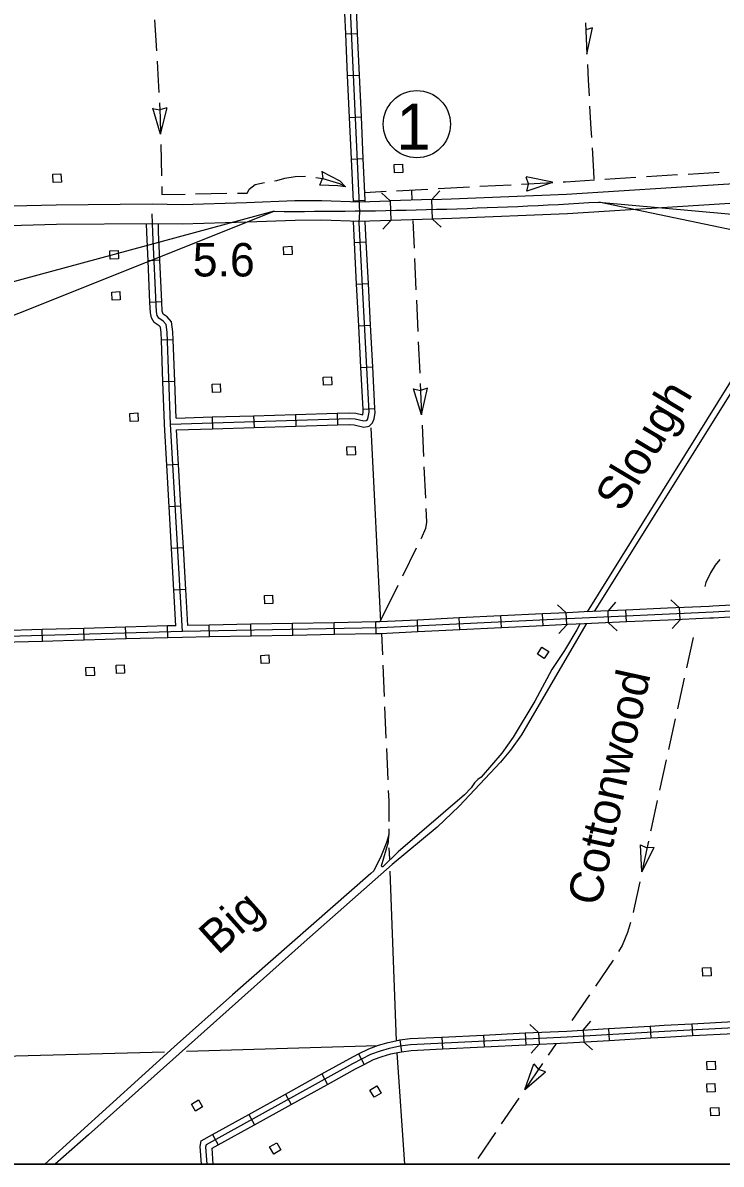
# Model space of a CAD drawing. Extents: x -0.3 to 2.65, y 0 to 1.9.
# Drawn here: x 0.6457 to 0.7514, y 0.1443 to 0.3171 of the extents above; entities that cross this region are included whole.
import ezdxf

# ---------------------------------------------------------------- set-up
doc = ezdxf.new("R2010")
doc.units = 0
for name, color, linetype in [('Default', 7, 'Continuous'), ('DSN_DRFT_DNC', 7, 'Continuous'), ('Level 12', 7, 'Continuous'), ('Level 14', 7, 'Continuous'), ('Level 15', 7, 'Continuous'), ('Level 16', 7, 'Continuous'), ('Level 19', 7, 'Continuous'), ('Level 20', 7, 'Continuous'), ('Level 21', 7, 'Continuous'), ('Level 29', 7, 'Continuous'), ('Level 30', 7, 'Continuous'), ('Level 6', 7, 'Continuous'), ('SHET_Annotations', 7, 'Continuous')]:
    doc.layers.add(name, color=color, linetype=linetype)

msp = doc.modelspace()

# ---------------------------------------------------------------- linework, layer by layer
at = {"layer": 'Default'}
for points in [[(0.97177, 0.24009), (0.73293, 0.28998), (0.80083, 0.28386)], [(0.45189, 0.196), (0.68371, 0.28858), (0.61638, 0.27038)]]:
    msp.add_lwpolyline(points, dxfattribs=at)
msp.add_arc((0.68669, 1.04739), 0.75882, 269.77499, 273.49367, dxfattribs=at)
at = {"layer": 'DSN_DRFT_DNC'}
msp.add_lwpolyline([(0.38477, 0.54167), (1.0319, 0.54167), (1.0319, 0.1443), (0.38477, 0.1443)], close=True, dxfattribs=at)
at = {"layer": 'Level 12'}
for p, q in [((0.73197, 0.31638), (0.73093, 0.31604)), ((0.73111, 0.31236), (0.73197, 0.31638)), ((0.66746, 0.30427), (0.66642, 0.30393)), ((0.66653, 0.30025), (0.66751, 0.30424)), ((0.66533, 0.30415), (0.6664, 0.30393)), ((0.66653, 0.30025), (0.66538, 0.30419)), ((0.69094, 0.29464), (0.69109, 0.29356)), ((0.69067, 0.29254), (0.69108, 0.29355)), ((0.72186, 0.29382), (0.72221, 0.29279)), ((0.72591, 0.29299), (0.72189, 0.2938)), ((0.72591, 0.29296), (0.72202, 0.29165)), ((0.72202, 0.29162), (0.72224, 0.29269)), ((0.70482, 0.26168), (0.70589, 0.26144)), ((0.70607, 0.25776), (0.70482, 0.26168)), ((0.70695, 0.26177), (0.70591, 0.26144)), ((0.70607, 0.25776), (0.70695, 0.26177)), ((0.73922, 0.19266), (0.7402, 0.19216)), ((0.73944, 0.18855), (0.73922, 0.19266)), ((0.73944, 0.18855), (0.7413, 0.19221)), ((0.7413, 0.19221), (0.74021, 0.19216)), ((0.7217, 0.15559), (0.72306, 0.15946)), ((0.72306, 0.15946), (0.72377, 0.15863)), ((0.7217, 0.15559), (0.72482, 0.15826)), ((0.72482, 0.15826), (0.72379, 0.15862))]:
    msp.add_line(p, q, dxfattribs=at)
for points in [[(0.66559, 0.31759), (0.66589, 0.31286)], [(0.73087, 0.3171), (0.73111, 0.31236)], [(0.66599, 0.31129), (0.66612, 0.30929), (0.66627, 0.30656)], [(0.73119, 0.31079), (0.73132, 0.30842)], [(0.73132, 0.30842), (0.73144, 0.30605)], [(0.66635, 0.30498), (0.66648, 0.30272), (0.66653, 0.30025)], [(0.73152, 0.30448), (0.7317, 0.30109), (0.73178, 0.29974)], [(0.66657, 0.29867), (0.66667, 0.29393)], [(0.73188, 0.29817), (0.7321, 0.2946), (0.73213, 0.29344)], [(0.68381, 0.29321), (0.68415, 0.29326), (0.68535, 0.29358), (0.68692, 0.29386), (0.68847, 0.29389), (0.68847, 0.29389)], [(0.69094, 0.29462), (0.69367, 0.29319), (0.69455, 0.29228), (0.69339, 0.29243), (0.69065, 0.29252)], [(0.74011, 0.29383), (0.74484, 0.29413)], [(0.74642, 0.29422), (0.75115, 0.29452)], [(0.66671, 0.29235), (0.66674, 0.29114), (0.67026, 0.29119)], [(0.67816, 0.29132), (0.67967, 0.29134), (0.67971, 0.2914), (0.67994, 0.29195), (0.68088, 0.29263), (0.68225, 0.29294)], [(0.69004, 0.29369), (0.69109, 0.29355), (0.69362, 0.29277), (0.69454, 0.29231)], [(0.70857, 0.29203), (0.7133, 0.29228)], [(0.71488, 0.29236), (0.71961, 0.29261)], [(0.72119, 0.2927), (0.72592, 0.29295)], [(0.7275, 0.29303), (0.72784, 0.29305), (0.73223, 0.29333)], [(0.73381, 0.29343), (0.73853, 0.29373)], [(0.67184, 0.29122), (0.67658, 0.2913)], [(0.69747, 0.29144), (0.70069, 0.29161)], [(0.70226, 0.29169), (0.70699, 0.29194)], [(0.70453, 0.29169), (0.70459, 0.29038)], [(0.70473, 0.2872), (0.70492, 0.28301)], [(0.70499, 0.28143), (0.70521, 0.2767)], [(0.70528, 0.27512), (0.70549, 0.27038)], [(0.70557, 0.26881), (0.70578, 0.26407)], [(0.70585, 0.26249), (0.70607, 0.25776)], [(0.70614, 0.25618), (0.70635, 0.25145)], [(0.70642, 0.24987), (0.70664, 0.24514)], [(0.70671, 0.24356), (0.7068, 0.2415), (0.70665, 0.24056), (0.70599, 0.23905), (0.70595, 0.23898)], [(0.70526, 0.23757), (0.70316, 0.23332)], [(0.75125, 0.23583), (0.75052, 0.23499), (0.7498, 0.23381), (0.74913, 0.23238), (0.74895, 0.23174)], [(0.70246, 0.2319), (0.69976, 0.22641)], [(0.69998, 0.22462), (0.70012, 0.2214)], [(0.7472, 0.22404), (0.74618, 0.21942)], [(0.70019, 0.21982), (0.70039, 0.21509)], [(0.74584, 0.21787), (0.74482, 0.21325)], [(0.70046, 0.21351), (0.70067, 0.20877)], [(0.74448, 0.2117), (0.74347, 0.20708)], [(0.70074, 0.2072), (0.70095, 0.20246)], [(0.74313, 0.20553), (0.74211, 0.2009)], [(0.70102, 0.20088), (0.70109, 0.19928), (0.7011, 0.19615)], [(0.74177, 0.19936), (0.74078, 0.19487), (0.74075, 0.19473)], [(0.74042, 0.19319), (0.73944, 0.18855)], [(0.73911, 0.18701), (0.73823, 0.18289), (0.7381, 0.18238)], [(0.73772, 0.18085), (0.73726, 0.17935), (0.73645, 0.1774), (0.7359, 0.17649)], [(0.73506, 0.17516), (0.73239, 0.17124)], [(0.7315, 0.16994), (0.72882, 0.16602)], [(0.72647, 0.16257), (0.72526, 0.1608)], [(0.72437, 0.1595), (0.7217, 0.15558)], [(0.72081, 0.15428), (0.71814, 0.15037)], [(0.71725, 0.14906), (0.71458, 0.14515)]]:
    msp.add_lwpolyline(points, dxfattribs=at)
at = {"layer": 'Level 14'}
for points in [[(0.76951, 0.2906), (0.75254, 0.2623), (0.73116, 0.2279)], [(0.7709, 0.29104), (0.75336, 0.26181), (0.7322, 0.22797)], [(0.73006, 0.22614), (0.72958, 0.22522), (0.72769, 0.22205), (0.72579, 0.21917), (0.72322, 0.21441), (0.71995, 0.20894), (0.7182, 0.20651), (0.71507, 0.20287), (0.7146, 0.20254), (0.71408, 0.202), (0.71356, 0.20126), (0.71257, 0.20022), (0.70253, 0.19155), (0.70018, 0.1893), (0.70003, 0.18928), (0.7, 0.18943), (0.70106, 0.19308), (0.7011, 0.19415), (0.70074, 0.19298), (0.69996, 0.19098), (0.69882, 0.18871), (0.69838, 0.18827), (0.6774, 0.1699), (0.66857, 0.16202), (0.64901, 0.14427)], [(0.73096, 0.22598), (0.72119, 0.20931), (0.71952, 0.20699), (0.718, 0.20515), (0.71174, 0.19849), (0.7084, 0.1953), (0.70163, 0.18967), (0.6883, 0.1779), (0.65563, 0.14874), (0.65057, 0.14427)], [(0.73106, 0.22614), (0.73096, 0.22598)], [(0.7011, 0.19504), (0.7011, 0.19415)], [(0.7011, 0.19504), (0.7011, 0.19415)], [(0.7011, 0.19457), (0.7011, 0.19415)]]:
    msp.add_lwpolyline(points, dxfattribs=at)
at = {"layer": 'Level 15'}
for p, q in [((0.69457, 0.31543), (0.69637, 0.31551)), ((0.69486, 0.30912), (0.69666, 0.3092)), ((0.69515, 0.3028), (0.69695, 0.30289)), ((0.69544, 0.29649), (0.69724, 0.29658)), ((0.69573, 0.29018), (0.69753, 0.29026)), ((0.69589, 0.28387), (0.69768, 0.28396)), ((0.66643, 0.28116), (0.66464, 0.28108)), ((0.69622, 0.27756), (0.69801, 0.27765)), ((0.66671, 0.27485), (0.66492, 0.27477)), ((0.69655, 0.27125), (0.69834, 0.27134)), ((0.66845, 0.26913), (0.66665, 0.26907)), ((0.69688, 0.26494), (0.69867, 0.26503)), ((0.66867, 0.26282), (0.66688, 0.26275)), ((0.68063, 0.25762), (0.68069, 0.25583)), ((0.68695, 0.25782), (0.687, 0.25603)), ((0.69326, 0.25802), (0.69332, 0.25622)), ((0.6972, 0.25863), (0.699, 0.25872)), ((0.67432, 0.25743), (0.67437, 0.25563)), ((0.66926, 0.25021), (0.66747, 0.25011)), ((0.66962, 0.24391), (0.66783, 0.2438)), ((0.66999, 0.2376), (0.66819, 0.2375)), ((0.67035, 0.23129), (0.66855, 0.23119)), ((0.73708, 0.22639), (0.737, 0.22818)), ((0.74523, 0.22675), (0.74515, 0.22854)), ((0.70552, 0.22489), (0.70544, 0.22668)), ((0.71184, 0.2252), (0.71175, 0.22699)), ((0.71815, 0.2255), (0.71806, 0.2273)), ((0.72446, 0.22581), (0.72437, 0.2276)), ((0.72804, 0.22599), (0.72796, 0.22778)), ((0.73438, 0.22627), (0.7343, 0.22806)), ((0.64866, 0.22344), (0.64861, 0.22524)), ((0.65498, 0.22363), (0.65493, 0.22542)), ((0.6613, 0.22381), (0.66124, 0.2256)), ((0.66761, 0.22399), (0.66756, 0.22578)), ((0.67392, 0.22413), (0.67389, 0.22592)), ((0.68024, 0.22425), (0.6802, 0.22604)), ((0.68655, 0.22436), (0.68652, 0.22616)), ((0.69287, 0.22448), (0.69284, 0.22628)), ((0.69919, 0.2246), (0.69915, 0.22639)), ((0.72377, 0.16423), (0.72385, 0.16247)), ((0.73053, 0.16456), (0.73062, 0.1628)), ((0.73437, 0.16482), (0.73447, 0.16302)), ((0.74068, 0.16519), (0.74078, 0.1634)), ((0.74699, 0.16554), (0.74708, 0.16375)), ((0.70276, 0.16308), (0.70301, 0.1613)), ((0.70914, 0.16353), (0.70923, 0.16173)), ((0.71545, 0.16383), (0.71554, 0.16204)), ((0.72176, 0.16414), (0.72185, 0.16234)), ((0.69653, 0.16097), (0.69735, 0.15937)), ((0.69096, 0.15793), (0.69183, 0.15636)), ((0.68543, 0.15487), (0.6863, 0.1533)), ((0.6799, 0.15181), (0.68077, 0.15024)), ((0.67438, 0.14875), (0.67525, 0.14718))]:
    msp.add_line(p, q, dxfattribs=at)
for points in [[(0.69662, 0.28688), (0.69669, 0.28847), (0.69377, 0.35203)], [(0.69457, 0.31543), (0.69428, 0.32174)], [(0.69637, 0.31551), (0.69608, 0.32182)], [(0.69486, 0.30912), (0.69457, 0.31543)], [(0.69666, 0.3092), (0.69637, 0.31551)], [(0.69515, 0.3028), (0.69486, 0.30912)], [(0.69695, 0.30289), (0.69666, 0.3092)], [(0.69544, 0.29649), (0.69515, 0.3028)], [(0.69724, 0.29658), (0.69695, 0.30289)], [(0.69574, 0.29005), (0.69544, 0.29649)], [(0.69753, 0.29026), (0.69724, 0.29658)], [(0.69754, 0.29004), (0.69753, 0.29026)], [(0.66536, 0.28539), (0.66527, 0.2882)], [(0.69589, 0.28387), (0.69573, 0.28705)], [(0.69768, 0.28396), (0.69752, 0.28705)], [(0.66464, 0.28108), (0.66445, 0.28535), (0.6644, 0.28669)], [(0.66983, 0.22493), (0.66803, 0.25635), (0.66752, 0.27025), (0.66736, 0.27144), (0.66692, 0.27193), (0.66627, 0.27238), (0.66603, 0.2728), (0.6659, 0.27334), (0.66536, 0.28539)], [(0.66643, 0.28116), (0.66624, 0.28542), (0.6662, 0.28668)], [(0.66803, 0.25635), (0.69521, 0.2572), (0.69599, 0.25716), (0.69733, 0.25683), (0.69767, 0.25689), (0.69785, 0.25707), (0.69798, 0.25739), (0.69811, 0.25817), (0.69662, 0.28688)], [(0.69622, 0.27756), (0.69589, 0.28387)], [(0.69801, 0.27765), (0.69768, 0.28396)], [(0.66492, 0.27477), (0.66464, 0.28108)], [(0.66671, 0.27485), (0.66643, 0.28116)], [(0.69655, 0.27125), (0.69622, 0.27756)], [(0.69834, 0.27134), (0.69801, 0.27765)], [(0.66845, 0.26913), (0.6684, 0.27032), (0.6682, 0.27183), (0.66751, 0.27259), (0.66693, 0.27299), (0.66685, 0.27313), (0.66677, 0.27346), (0.66671, 0.27485)], [(0.66665, 0.26907), (0.66661, 0.27017), (0.6665, 0.27104), (0.66632, 0.27124), (0.66558, 0.27174), (0.66517, 0.27246), (0.66499, 0.27321), (0.66492, 0.27477)], [(0.69688, 0.26494), (0.69655, 0.27125)], [(0.69867, 0.26503), (0.69834, 0.27134)], [(0.66688, 0.26275), (0.66665, 0.26907)], [(0.66867, 0.26282), (0.66845, 0.26913)], [(0.6972, 0.25863), (0.69688, 0.26494)], [(0.699, 0.25872), (0.69867, 0.26503)], [(0.66711, 0.25644), (0.66688, 0.26275)], [(0.66888, 0.25726), (0.66867, 0.26282)], [(0.67432, 0.25743), (0.68063, 0.25762)], [(0.68063, 0.25762), (0.68695, 0.25782)], [(0.68695, 0.25782), (0.69326, 0.25802)], [(0.69326, 0.25802), (0.69521, 0.25808), (0.69611, 0.25803), (0.69715, 0.25778), (0.69723, 0.25823), (0.6972, 0.25863)], [(0.69332, 0.25622), (0.6952, 0.25628), (0.69585, 0.25625), (0.6973, 0.2559), (0.69812, 0.25605), (0.69862, 0.25656), (0.69886, 0.25713), (0.69903, 0.25812), (0.699, 0.25872)], [(0.66747, 0.25011), (0.66712, 0.25631), (0.66711, 0.25644)], [(0.66888, 0.25726), (0.67432, 0.25743)], [(0.67437, 0.25563), (0.68069, 0.25583)], [(0.68069, 0.25583), (0.687, 0.25603)], [(0.687, 0.25603), (0.69332, 0.25622)], [(0.66896, 0.25546), (0.67437, 0.25563)], [(0.66926, 0.25021), (0.66896, 0.25546)], [(0.66783, 0.2438), (0.66747, 0.25011)], [(0.66962, 0.24391), (0.66926, 0.25021)], [(0.66819, 0.2375), (0.66783, 0.2438)], [(0.66999, 0.2376), (0.66962, 0.24391)], [(0.66855, 0.23119), (0.66819, 0.2375)], [(0.67035, 0.23129), (0.66999, 0.2376)], [(0.79381, 0.23038), (0.75023, 0.22785), (0.72816, 0.22687), (0.69981, 0.22549), (0.66983, 0.22493), (0.63989, 0.22407), (0.62307, 0.22321), (0.60838, 0.22257), (0.57684, 0.22085), (0.5607, 0.22017), (0.51339, 0.2177), (0.51266, 0.21786), (0.5116, 0.21849), (0.51058, 0.21877), (0.50863, 0.219)], [(0.66886, 0.22582), (0.66855, 0.23119)], [(0.67066, 0.22586), (0.67035, 0.23129)], [(0.737, 0.22818), (0.73068, 0.2279)], [(0.74331, 0.22846), (0.737, 0.22818)], [(0.74962, 0.22874), (0.74331, 0.22846)], [(0.75592, 0.2291), (0.75018, 0.22877), (0.74962, 0.22874)], [(0.70544, 0.22668), (0.69978, 0.22641), (0.69915, 0.22639)], [(0.71175, 0.22699), (0.70544, 0.22668)], [(0.71806, 0.2273), (0.71175, 0.22699)], [(0.72437, 0.2276), (0.71806, 0.2273)], [(0.73068, 0.2279), (0.72812, 0.22779), (0.72437, 0.2276)], [(0.74339, 0.22667), (0.73708, 0.22639)], [(0.7497, 0.22695), (0.74339, 0.22667)], [(0.75602, 0.22731), (0.75028, 0.22697), (0.7497, 0.22695)], [(0.64861, 0.22524), (0.6423, 0.22506)], [(0.65493, 0.22542), (0.64861, 0.22524)], [(0.66124, 0.2256), (0.65493, 0.22542)], [(0.66756, 0.22578), (0.66124, 0.2256)], [(0.66886, 0.22582), (0.66756, 0.22578)], [(0.67389, 0.22592), (0.67066, 0.22586)], [(0.6802, 0.22604), (0.67389, 0.22592)], [(0.68652, 0.22616), (0.6802, 0.22604)], [(0.69284, 0.22628), (0.68652, 0.22616)], [(0.69915, 0.22639), (0.69284, 0.22628)], [(0.70552, 0.22489), (0.69984, 0.22461), (0.69919, 0.2246)], [(0.71184, 0.2252), (0.70552, 0.22489)], [(0.71815, 0.2255), (0.71184, 0.2252)], [(0.72446, 0.22581), (0.71815, 0.2255)], [(0.73076, 0.22611), (0.7282, 0.22599), (0.72446, 0.22581)], [(0.73708, 0.22639), (0.73076, 0.22611)], [(0.64866, 0.22344), (0.64235, 0.22326)], [(0.65498, 0.22363), (0.64866, 0.22344)], [(0.6613, 0.22381), (0.65498, 0.22363)], [(0.66761, 0.22399), (0.6613, 0.22381)], [(0.67392, 0.22413), (0.66985, 0.22405), (0.66761, 0.22399)], [(0.68024, 0.22425), (0.67392, 0.22413)], [(0.68655, 0.22436), (0.68024, 0.22425)], [(0.69287, 0.22448), (0.68655, 0.22436)], [(0.69919, 0.2246), (0.69287, 0.22448)], [(0.67359, 0.14427), (0.67341, 0.14691), (0.67348, 0.14725), (0.69563, 0.15951), (0.6984, 0.16095), (0.69983, 0.16145), (0.70119, 0.16185), (0.70279, 0.16219), (0.70441, 0.16242), (0.72812, 0.16356), (0.74285, 0.16444), (0.79559, 0.16721)], [(0.72176, 0.16414), (0.72807, 0.16444)], [(0.72807, 0.16444), (0.72807, 0.16444), (0.73437, 0.16482)], [(0.73437, 0.16482), (0.74068, 0.16519)], [(0.74068, 0.16519), (0.7428, 0.16532), (0.74699, 0.16554)], [(0.74699, 0.16554), (0.7533, 0.16587)], [(0.69653, 0.16097), (0.69805, 0.16176), (0.69956, 0.16229), (0.70098, 0.1627), (0.70264, 0.16306), (0.70276, 0.16308)], [(0.70276, 0.16308), (0.70433, 0.16329), (0.70914, 0.16353)], [(0.70914, 0.16353), (0.71545, 0.16383)], [(0.71545, 0.16383), (0.72176, 0.16414)], [(0.72185, 0.16234), (0.72816, 0.16265)], [(0.72816, 0.16265), (0.72816, 0.16265), (0.73447, 0.16302)], [(0.73447, 0.16302), (0.74078, 0.1634)], [(0.74078, 0.1634), (0.7429, 0.16353), (0.74708, 0.16375)], [(0.74708, 0.16375), (0.75339, 0.16408)], [(0.69096, 0.15793), (0.69521, 0.16029), (0.69653, 0.16097)], [(0.69735, 0.15937), (0.69877, 0.16011), (0.70011, 0.16058), (0.70141, 0.16096), (0.70295, 0.16129), (0.70301, 0.1613)], [(0.70301, 0.1613), (0.7045, 0.1615), (0.70923, 0.16173)], [(0.70923, 0.16173), (0.71554, 0.16204)], [(0.71554, 0.16204), (0.72185, 0.16234)], [(0.69183, 0.15636), (0.69606, 0.1587), (0.69735, 0.15937)], [(0.68543, 0.15487), (0.69096, 0.15793)], [(0.6863, 0.1533), (0.69183, 0.15636)], [(0.6799, 0.15181), (0.68543, 0.15487)], [(0.68077, 0.15024), (0.6863, 0.1533)], [(0.67438, 0.14875), (0.6799, 0.15181)], [(0.67271, 0.14427), (0.67253, 0.14697), (0.6727, 0.14782), (0.67438, 0.14875)], [(0.67525, 0.14718), (0.68077, 0.15024)], [(0.67451, 0.14427), (0.67435, 0.14668), (0.67525, 0.14718)]]:
    msp.add_lwpolyline(points, dxfattribs=at)
at = {"layer": 'Level 19'}
for points in [[(0.70198, 0.2944), (0.70193, 0.29565), (0.70318, 0.2957), (0.70323, 0.29446)], [(0.65025, 0.29295), (0.6502, 0.29419), (0.65144, 0.29425), (0.6515, 0.293)], [(0.6589, 0.28135), (0.65885, 0.28259), (0.6601, 0.28265), (0.66015, 0.2814)], [(0.6852, 0.28198), (0.68515, 0.28322), (0.6864, 0.28328), (0.68645, 0.28203)], [(0.65918, 0.27511), (0.65913, 0.27635), (0.66038, 0.27641), (0.66043, 0.27516)], [(0.69121, 0.26223), (0.69116, 0.26347), (0.69241, 0.26353), (0.69246, 0.26228)], [(0.67437, 0.26113), (0.67432, 0.26238), (0.67557, 0.26243), (0.67562, 0.26118)], [(0.66191, 0.25674), (0.66186, 0.25798), (0.6631, 0.25804), (0.66316, 0.25679)], [(0.69479, 0.25165), (0.69474, 0.25289), (0.69598, 0.25294), (0.69604, 0.2517)], [(0.6823, 0.22913), (0.68225, 0.23037), (0.6835, 0.23043), (0.68355, 0.22918)], [(0.68175, 0.22009), (0.6817, 0.22133), (0.68294, 0.22139), (0.683, 0.22014)], [(0.72465, 0.22085), (0.72361, 0.22153), (0.7243, 0.22258), (0.72534, 0.22189)], [(0.65527, 0.21825), (0.65522, 0.21949), (0.65647, 0.21955), (0.65652, 0.2183)], [(0.65983, 0.2186), (0.65978, 0.21985), (0.66103, 0.2199), (0.66108, 0.21865)], [(0.74867, 0.17275), (0.74862, 0.17399), (0.74987, 0.17404), (0.74992, 0.1728)], [(0.74934, 0.15858), (0.74928, 0.15983), (0.75053, 0.15988), (0.75058, 0.15863)], [(0.69888, 0.1544), (0.69823, 0.15547), (0.6993, 0.15612), (0.69995, 0.15505)], [(0.74931, 0.15519), (0.74925, 0.15643), (0.7505, 0.15649), (0.75055, 0.15524)], [(0.67183, 0.1523), (0.67119, 0.15337), (0.67226, 0.15401), (0.6729, 0.15295)], [(0.7499, 0.15158), (0.74985, 0.15282), (0.75109, 0.15287), (0.75115, 0.15163)], [(0.68369, 0.14581), (0.68305, 0.14688), (0.68412, 0.14752), (0.68476, 0.14646)]]:
    msp.add_lwpolyline(points, close=True, dxfattribs=at)
at = {"layer": 'Level 20'}
msp.add_line((0.70232, 0.16112), (0.70347, 0.14427), dxfattribs=at)
for points in [[(0.69836, 0.25579), (0.69983, 0.22641)], [(0.70112, 0.19216), (0.70119, 0.19048)], [(0.70125, 0.18865), (0.70221, 0.16293)], [(0.58102, 0.15722), (0.64276, 0.16062), (0.6671, 0.16131)], [(0.67045, 0.16141), (0.69937, 0.16223)]]:
    msp.add_lwpolyline(points, dxfattribs=at)
at = {"layer": 'Level 21'}
for points in [[(0.70763, 0.29038), (0.71056, 0.29048), (0.728, 0.29117), (0.75971, 0.29317), (0.76686, 0.29373)], [(0.76708, 0.29075), (0.75992, 0.29019), (0.72816, 0.28818), (0.71067, 0.28749), (0.70771, 0.28739)], [(0.6401, 0.28926), (0.64177, 0.28934), (0.6507, 0.28958), (0.66527, 0.28969), (0.66979, 0.28962), (0.67952, 0.2899), (0.68687, 0.2902), (0.69098, 0.29023), (0.69668, 0.29001), (0.70132, 0.29017)], [(0.70131, 0.29017), (0.70141, 0.28718)], [(0.70763, 0.29038), (0.70132, 0.29017)], [(0.70772, 0.28739), (0.70762, 0.29038)], [(0.70141, 0.28718), (0.69668, 0.28702), (0.69094, 0.28724), (0.68694, 0.28721), (0.67963, 0.28691), (0.66981, 0.28662), (0.66526, 0.2867), (0.65075, 0.28659), (0.64189, 0.28635), (0.64024, 0.28627)], [(0.70771, 0.28739), (0.70141, 0.28718)]]:
    msp.add_lwpolyline(points, dxfattribs=at)
at = {"layer": 'Level 29'}
for points in [[(0.72663, 0.22897), (0.72796, 0.22776)], [(0.7343, 0.22804), (0.73551, 0.22937)], [(0.74383, 0.22974), (0.74515, 0.22853)], [(0.74523, 0.22673), (0.74402, 0.22541)], [(0.72805, 0.22597), (0.72684, 0.22464)], [(0.7357, 0.22504), (0.73438, 0.22625)], [(0.72244, 0.16543), (0.72377, 0.16422)], [(0.73053, 0.16459), (0.73172, 0.16593)], [(0.73193, 0.16161), (0.73059, 0.1628)], [(0.72386, 0.16243), (0.72265, 0.1611)]]:
    msp.add_lwpolyline(points, dxfattribs=at)
at = {"layer": 'Level 30'}
for points in [[(0.7, 0.29139), (0.70131, 0.29017)], [(0.70762, 0.29038), (0.70884, 0.29169)], [(0.70141, 0.28718), (0.70019, 0.28587)], [(0.70903, 0.28617), (0.70772, 0.28739)]]:
    msp.add_lwpolyline(points, dxfattribs=at)
at = {"layer": 'Level 6'}
msp.add_line((0.38476, 0.14427), (1.03189, 0.14427), dxfattribs=at)
at = {"layer": 'SHET_Annotations'}
msp.add_circle((0.70535, 0.30177), 0.00509, dxfattribs=at)

# ---------------------------------------------------------------- texts
at = {"layer": 'Level 12'}
msp.add_text('Cottonwood', height=0.005055, rotation=77.6309, dxfattribs=at).set_placement((0.73305, 0.18322))
at = {"layer": 'Level 14'}
for s, rotation, p in [('Slough', 59.1761, (0.73645, 0.24285)), ('Big', 41.9582, (0.67523, 0.17583))]:
    msp.add_text(s, height=0.005055, rotation=rotation, dxfattribs=at).set_placement(p)
at = {"layer": 'Level 16'}
msp.add_text('5.6', height=0.005055, dxfattribs=at).set_placement((0.6714, 0.27871))
at = {"layer": 'SHET_Annotations'}
msp.add_text('1', height=0.007, dxfattribs=at).set_placement((0.70223, 0.29789))

doc.saveas('drawing.dxf')
